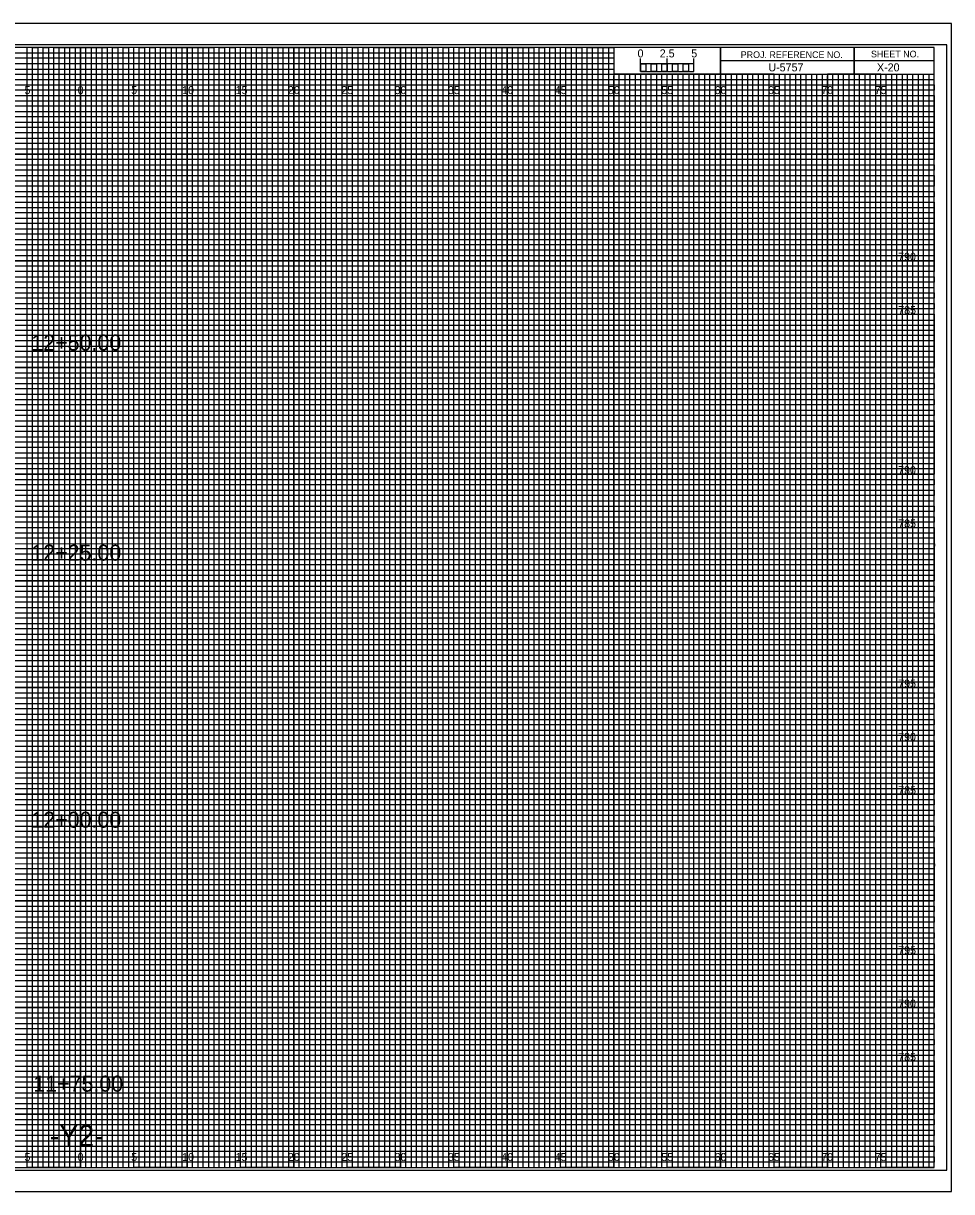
# Model space of a CAD drawing. Extents: x -7 to 162, y 108 to 217.
# Drawn here: x 74.6 to 161.7, y 107.7 to 217.2 of the extents above; entities that cross this region are included whole.
import ezdxf

# ---------------------------------------------------------------- set-up
doc = ezdxf.new("R2010")
doc.units = 0
for name, color, linetype in [('Exist Cross Section Cell', 7, 'Continuous'), ('Exist XS Center Line Elevation Label', 7, 'Continuous'), ('Prop CMT Pvmt Course 2 Wedge', 7, 'Continuous'), ('Prop XS Alignment Label', 7, 'Continuous'), ('Prop XS Bar Scale Labels', 7, 'Continuous'), ('Prop XS Hydro Elevations', 7, 'Continuous'), ('Prop XS Project Number', 7, 'Continuous'), ('Prop XS Retaining Wall', 7, 'Continuous'), ('Prop XS SE Text', 7, 'Continuous'), ('Prop XS Sheet Number', 7, 'Continuous'), ('Prop XS Side Slope Text', 7, 'Continuous'), ('Sheet Cross Section Scale CELL', 7, 'Continuous'), ('Sheet Cutting Line CELL', 7, 'Continuous'), ('Sheet DOT Grid CELL', 7, 'Continuous'), ('Sheet Plot Border Inside CELL', 7, 'Continuous'), ('Sheet Plot Border Outside CELL', 7, 'Continuous')]:
    doc.layers.add(name, color=color, linetype=linetype)

msp = doc.modelspace()

# ---------------------------------------------------------------- linework, layer by layer
at = {"layer": 'Exist Cross Section Cell'}
for p, q in [((75, 215), (70, 215)), ((75, 110), (75, 215)), ((85, 215), (80, 215)), ((80, 215), (80, 110)), ((85, 110), (85, 215)), ((95, 215), (90, 215)), ((90, 215), (90, 110)), ((95, 110), (95, 215)), ((105, 215), (100, 215)), ((100, 215), (100, 110)), ((105, 110), (105, 215)), ((115, 215), (110, 215)), ((110, 215), (110, 110)), ((115, 110), (115, 215)), ((125, 215), (120, 215)), ((120, 215), (120, 110)), ((125, 110), (125, 215)), ((130, 215), (130, 110)), ((135, 110), (135, 212.5)), ((145, 212.5), (140, 212.5)), ((140, 212.5), (140, 110)), ((145, 110), (145, 212.5)), ((155, 212.5), (150, 212.5)), ((150, 212.5), (150, 110)), ((155, 110), (155, 212.5)), ((80, 110), (75, 110)), ((90, 110), (85, 110)), ((100, 110), (95, 110)), ((110, 110), (105, 110)), ((120, 110), (115, 110)), ((130, 110), (125, 110)), ((140, 110), (135, 110)), ((150, 110), (145, 110)), ((160, 110), (155, 110)), ((160, 110), (160, 110))]:
    msp.add_line(p, q, dxfattribs=at)
for points in [[(0, 210), (160, 210), (160, 205), (0, 205)], [(0, 200), (160, 200), (160, 195), (0, 195)], [(0, 190), (160, 190), (160, 185), (0, 185)], [(0, 180), (160, 180), (160, 175), (0, 175)], [(0, 170), (160, 170), (160, 165), (0, 165)], [(0, 160), (160, 160), (160, 155), (0, 155)], [(0, 150), (160, 150), (160, 145), (0, 145)], [(0, 140), (160, 140), (160, 135), (0, 135)], [(0, 130), (160, 130), (160, 125), (0, 125)], [(0, 120), (160, 120), (160, 115), (0, 115)]]:
    msp.add_lwpolyline(points, dxfattribs=at)
at = {"layer": 'Exist XS Center Line Elevation Label'}
for points in [[(72.5, 110), (77.5, 110), (77.5, 215), (82.5, 215), (82.5, 110), (87.5, 110), (87.5, 215), (92.5, 215), (92.5, 110), (97.5, 110), (97.5, 215), (102.5, 215), (102.5, 110), (107.5, 110), (107.5, 215), (112.5, 215), (112.5, 110), (117.5, 110), (117.5, 215), (122.5, 215), (122.5, 110), (127.5, 110), (127.5, 215), (129.97, 215), (130, 215), (130, 212.5), (132.5, 212.5), (132.5, 110), (137.5, 110), (137.5, 212.5), (142.5, 212.5), (142.5, 110), (147.5, 110), (147.5, 212.5), (152.5, 212.5), (152.5, 110), (157.5, 110), (157.5, 212.5)], [(0, 212.5), (137.5, 212.5)], [(0, 202.5), (160, 202.5), (160, 207.5), (0, 207.5)], [(0, 192.5), (160, 192.5), (160, 197.5), (0, 197.5)], [(0, 182.5), (160, 182.5), (160, 187.5), (0, 187.5)], [(0, 172.5), (160, 172.5), (160, 177.5), (0, 177.5)], [(0, 162.5), (160, 162.5), (160, 167.5), (0, 167.5)], [(0, 152.5), (160, 152.5), (160, 157.5), (0, 157.5)], [(0, 142.5), (160, 142.5), (160, 147.5), (0, 147.5)], [(0, 132.5), (160, 132.5), (160, 137.5), (0, 137.5)], [(0, 122.5), (160, 122.5), (160, 127.5), (0, 127.5)], [(0, 112.5), (160, 112.5), (160, 117.5), (0, 117.5)]]:
    msp.add_lwpolyline(points, dxfattribs=at)
at = {"layer": 'Prop XS Hydro Elevations'}
for p, q in [((152.5, 215), (152.5, 212.5)), ((152.5, 212.5), (152.5, 215)), ((160, 213.75), (140, 213.75)), ((140, 213.75), (140, 212.5)), ((140, 212.5), (160, 212.5))]:
    msp.add_line(p, q, dxfattribs=at)
for points in [[(160, 215), (0, 215), (0, 110), (160, 110)], [(140, 215), (130, 215), (130, 212.52), (140, 212.52)], [(160, 215), (140, 215), (140, 212.5), (160, 212.5)]]:
    msp.add_lwpolyline(points, close=True, dxfattribs=at)
at = {"layer": 'Prop XS Retaining Wall'}
for p, q in [((133.5, 212.5), (133, 212.5)), ((133, 212.5), (133, 110)), ((133.5, 110), (133.5, 212.5)), ((134.5, 212.5), (134, 212.5)), ((134, 212.5), (134, 110)), ((134.5, 110), (134.5, 212.5)), ((133, 110), (132.5, 110)), ((134, 110), (133.5, 110))]:
    msp.add_line(p, q, dxfattribs=at)
for points in [[(75, 110), (75.5, 110), (75.5, 215), (76, 215), (76, 110)], [(76, 110), (76.5, 110), (76.5, 215), (77, 215), (77, 110)], [(77.5, 110), (78, 110), (78, 215), (78.5, 215), (78.5, 110)], [(78.5, 110), (79, 110), (79, 215), (79.5, 215), (79.5, 110)], [(80, 110), (80.5, 110), (80.5, 215), (81, 215), (81, 110)], [(81, 110), (81.5, 110), (81.5, 215), (82, 215), (82, 110)], [(82.5, 110), (83, 110), (83, 215), (83.5, 215), (83.5, 110)], [(83.5, 110), (84, 110), (84, 215), (84.5, 215), (84.5, 110)], [(85, 110), (85.5, 110), (85.5, 215), (86, 215), (86, 110)], [(86, 110), (86.5, 110), (86.5, 215), (87, 215), (87, 110)], [(87.5, 110), (88, 110), (88, 215), (88.5, 215), (88.5, 110)], [(88.5, 110), (89, 110), (89, 215), (89.5, 215), (89.5, 110)], [(90, 110), (90.5, 110), (90.5, 215), (91, 215), (91, 110)], [(91, 110), (91.5, 110), (91.5, 215), (92, 215), (92, 110)], [(92.5, 110), (93, 110), (93, 215), (93.5, 215), (93.5, 110)], [(93.5, 110), (94, 110), (94, 215), (94.5, 215), (94.5, 110)], [(95, 110), (95.5, 110), (95.5, 215), (96, 215), (96, 110)], [(96, 110), (96.5, 110), (96.5, 215), (97, 215), (97, 110)], [(97.5, 110), (98, 110), (98, 215), (98.5, 215), (98.5, 110)], [(98.5, 110), (99, 110), (99, 215), (99.5, 215), (99.5, 110)], [(100, 110), (100.5, 110), (100.5, 215), (101, 215), (101, 110)], [(101, 110), (101.5, 110), (101.5, 215), (102, 215), (102, 110)], [(102.5, 110), (103, 110), (103, 215), (103.5, 215), (103.5, 110)], [(103.5, 110), (104, 110), (104, 215), (104.5, 215), (104.5, 110)], [(105, 110), (105.5, 110), (105.5, 215), (106, 215), (106, 110)], [(106, 110), (106.5, 110), (106.5, 215), (107, 215), (107, 110)], [(107.5, 110), (108, 110), (108, 215), (108.5, 215), (108.5, 110)], [(108.5, 110), (109, 110), (109, 215), (109.5, 215), (109.5, 110)], [(110, 110), (110.5, 110), (110.5, 215), (111, 215), (111, 110)], [(111, 110), (111.5, 110), (111.5, 215), (112, 215), (112, 110)], [(112.5, 110), (113, 110), (113, 215), (113.5, 215), (113.5, 110)], [(113.5, 110), (114, 110), (114, 215), (114.5, 215), (114.5, 110)], [(115, 110), (115.5, 110), (115.5, 215), (116, 215), (116, 110)], [(116, 110), (116.5, 110), (116.5, 215), (117, 215), (117, 110)], [(117.5, 110), (118, 110), (118, 215), (118.5, 215), (118.5, 110)], [(118.5, 110), (119, 110), (119, 215), (119.5, 215), (119.5, 110)], [(120, 110), (120.5, 110), (120.5, 215), (121, 215), (121, 110)], [(121, 110), (121.5, 110), (121.5, 215), (122, 215), (122, 110)], [(122.5, 110), (123, 110), (123, 215), (123.5, 215), (123.5, 110)], [(123.5, 110), (124, 110), (124, 215), (124.5, 215), (124.5, 110)], [(125, 110), (125.5, 110), (125.5, 215), (126, 215), (126, 110)], [(126, 110), (126.5, 110), (126.5, 215), (127, 215), (127, 110)], [(127.5, 110), (128, 110), (128, 215), (128.5, 215), (128.5, 110)], [(128.5, 110), (129, 110), (129, 215), (129.5, 215), (129.5, 110)], [(130, 110), (130.5, 110), (130.5, 212.5), (131.01, 212.5), (131.01, 110)], [(131, 110), (131.5, 110), (131.5, 212.5), (132, 212.5), (132, 110)], [(135, 110), (135.49, 110), (135.49, 212.5), (136, 212.5), (136, 110)], [(136, 110), (136.5, 110), (136.5, 212.5), (137.03, 212.5), (137.03, 110)], [(137.5, 110), (138, 110), (138, 212.5), (138.5, 212.5), (138.5, 110)], [(138.5, 110), (139, 110), (139, 212.5), (139.5, 212.5), (139.5, 110)], [(140, 110), (140.5, 110), (140.5, 212.5), (141, 212.5), (141, 110)], [(141, 110), (141.5, 110), (141.5, 212.5), (142, 212.5), (142, 110)], [(142.5, 110), (143, 110), (143, 212.5), (143.5, 212.5), (143.5, 110)], [(143.5, 110), (144, 110), (144, 212.5), (144.5, 212.5), (144.5, 110)], [(145, 110), (145.5, 110), (145.5, 212.5), (146, 212.5), (146, 110)], [(146, 110), (146.5, 110), (146.5, 212.5), (147, 212.5), (147, 110)], [(147.5, 110), (148, 110), (148, 212.5), (148.5, 212.5), (148.5, 110)], [(148.5, 110), (149, 110), (149, 212.5), (149.5, 212.5), (149.5, 110)], [(150, 110), (150.5, 110), (150.5, 212.5), (151, 212.5), (151, 110)], [(151, 110), (151.5, 110), (151.5, 212.5), (152, 212.5), (152, 110)], [(152.5, 110), (153, 110), (153, 212.5), (153.5, 212.5), (153.5, 110)], [(153.5, 110), (154, 110), (154, 212.5), (154.5, 212.5), (154.5, 110)], [(155, 110), (155.5, 110), (155.5, 212.5), (156, 212.5), (156, 110)], [(156, 110), (156.5, 110), (156.5, 212.5), (157, 212.5), (157, 110)], [(157.5, 110), (158, 110), (158, 212.5), (158.5, 212.5), (158.5, 110)], [(158.5, 110), (159, 110), (159, 212.5), (159.5, 212.5), (159.5, 110)]]:
    msp.add_lwpolyline(points, dxfattribs=at)
at = {"layer": 'Prop XS Side Slope Text'}
for p, q in [((0, 214.5), (130, 214.5)), ((130, 213.99), (0, 213.99)), ((130, 214.5), (130, 213.99)), ((0, 213.5), (130, 213.5)), ((130, 212.94), (0, 212.94)), ((130, 213.5), (130, 212.94)), ((0, 212), (160, 212))]:
    msp.add_line(p, q, dxfattribs=at)
for points in [[(0, 211.5), (135, 211.5), (160, 211.5), (160, 211), (0, 211)], [(0, 210.5), (160, 210.5), (160, 209.5), (0, 209.5)], [(0, 209), (160, 209), (160, 208.5), (0, 208.49)], [(0, 208), (160, 208), (160, 207), (0, 207)], [(0, 206.5), (160, 206.5), (160, 206), (0, 206)], [(0, 205.5), (160, 205.5), (160, 204.5), (0, 204.5)], [(0, 204), (160, 204), (160, 203.5), (0, 203.5)], [(0, 203), (160, 203), (160, 202), (0, 202)], [(0, 201.5), (160, 201.5), (160, 201), (0, 201)], [(0, 200.5), (160, 200.5), (160, 199.5), (0, 199.5)], [(0, 199), (160, 199), (160, 198.5), (0, 198.5)], [(0, 198), (160, 198), (160, 196.97), (160, 196.5), (160, 196), (0, 196)], [(0, 197), (160, 197), (160, 196.5), (0, 196.5)], [(0, 195.5), (160, 195.5), (160, 194.5), (0, 194.52)], [(0, 194.52), (160, 194.5), (160, 194), (0, 194)], [(0, 193.5), (160, 193.5), (160, 193), (0, 193)], [(0, 192), (160, 192), (160, 191.5), (0, 191.5)], [(0, 191), (160, 191), (160, 190.5), (0, 190.5)], [(-0.04, 189.44), (160, 189.44), (160, 188.94), (-0.04, 188.94)], [(0, 188.5), (160, 188.5), (160, 188), (0, 188)], [(0, 187), (160, 187), (160, 186.5), (0, 186.5)], [(0, 186), (160, 186), (160, 185.5), (0, 185.5)], [(0, 184.5), (160, 184.5), (160, 184), (0, 184)], [(0, 183.5), (160, 183.5), (160, 183), (0, 183)], [(0, 182), (160, 182), (160, 181.5), (0, 181.5)], [(0, 181), (160, 181), (160, 180.5), (0, 180.5)], [(0, 179.5), (160, 179.5), (160, 178.99), (0, 179)], [(0, 178.5), (160, 178.5), (160, 178), (0, 178)], [(0, 177), (160, 177), (160, 176.5), (0, 176.5)], [(0, 176), (160, 176), (160, 175.5), (0, 175.5)], [(0, 174.5), (160, 174.5), (160, 174), (0, 174)], [(0, 173.5), (160, 173.5), (160, 173), (0, 173)], [(0, 172), (160, 172), (160, 171.5), (0, 171.5)], [(0, 171), (160, 171), (160, 170.5), (0, 170.5)], [(0, 169.5), (160, 169.5), (160, 169), (0, 169)], [(0, 168.5), (160.03, 168.46), (160, 168), (0, 168)], [(0, 167), (160, 167), (160, 166.5), (0, 166.5)], [(0, 166), (160, 166), (160, 165.5), (0, 165.5)], [(0, 164.5), (160, 164.5), (160, 164), (0, 164)], [(0, 163.5), (160, 163.5), (160, 163), (0, 163)], [(0, 162), (160, 162), (160, 161.5), (0, 161.5)], [(0, 161), (160, 161), (160, 160.5), (0, 160.5)], [(0, 159.5), (160, 159.5), (160, 159), (0, 159)], [(0, 158.5), (160, 158.5), (160, 158), (0, 158)], [(0, 157), (160, 157), (160, 156.5), (0, 156.5)], [(0, 156), (160, 156), (160, 155.5), (0, 155.5)], [(0, 154.5), (160, 154.5), (160, 154), (0, 154)], [(0, 153.5), (160, 153.5), (160, 153), (0, 153)], [(0, 152), (160, 152), (160, 151.5), (0, 151.5)], [(0, 151), (160, 151), (160, 150.5), (0, 150.5)], [(0, 149.5), (160, 149.5), (160, 148.99), (0, 149)], [(0, 148.5), (160, 148.5), (160, 148), (0, 148)], [(0, 147), (160, 147), (160, 146.5), (0, 146.5)], [(0, 146), (160, 146), (160, 145.5), (0, 145.5)], [(0, 144.5), (160, 144.5), (160, 144), (0, 144)], [(0, 143.5), (160, 143.5), (160, 143), (0, 143)], [(0, 142), (160, 142), (160, 141.5), (0, 141.5)], [(0, 141), (160, 141), (160, 140.5), (0, 140.5)], [(0, 139.5), (160, 139.5), (160, 139), (0, 139)], [(0, 138.5), (160.03, 138.46), (160, 138), (0, 138)], [(0, 137), (160, 137), (160, 136.5), (0, 136.5)], [(0, 136), (160, 136), (160, 135.5), (0, 135.5)], [(0, 134.5), (160, 134.5), (160, 134), (0, 134)], [(0, 133.5), (160, 133.5), (160, 133), (0, 133)], [(0, 132), (160, 132), (160, 131.5), (0, 131.5)], [(0, 131), (160, 131), (160, 130.5), (0, 130.5)], [(0, 129.5), (160, 129.5), (160, 129), (0, 129)], [(0, 128.5), (160, 128.5), (160, 128), (0, 128)], [(0, 127), (160, 127), (160, 126.5), (0, 126.5)], [(0, 126), (160, 126), (160, 125.5), (0, 125.5)], [(0, 124.5), (160, 124.5), (160, 124), (0, 124)], [(0, 123.5), (160, 123.5), (160, 123), (0, 123)], [(0, 122), (160, 122), (160, 121.5), (0, 121.5)], [(0, 121), (160, 121), (160, 120.5), (0, 120.5)], [(0, 119.5), (160, 119.5), (160, 119), (0, 119)], [(0, 118.5), (160, 118.5), (160, 118), (0, 118)], [(0, 117), (160, 117), (160, 116.5), (0, 116.5)], [(0, 116), (160, 116), (160, 115.5), (0, 115.5)], [(0, 114.5), (160, 114.5), (160, 114), (0, 114)], [(0, 113.5), (160, 113.5), (160, 113), (0, 113)], [(0, 112), (160, 112), (160, 111.5), (0, 111.5)], [(0, 111), (160, 111), (160, 110.5), (0, 110.5)]]:
    msp.add_lwpolyline(points, dxfattribs=at)
at = {"layer": 'Sheet Cross Section Scale CELL'}
for p, q in [((132.5, 212.75), (132.5, 213.95)), ((132.5, 213.45), (132.5, 213.95)), ((135, 212.75), (135, 213.95)), ((137.5, 212.75), (137.5, 213.95)), ((137.5, 213.45), (137.5, 213.95))]:
    msp.add_line(p, q, dxfattribs=at)
for points in [[(137.5, 213.45), (132.5, 213.45), (132.5, 212.75), (137.5, 212.75)], [(132.5, 213.45), (133, 213.45), (133, 212.75), (132.5, 212.75)], [(133.5, 213.45), (134, 213.45), (134, 212.75), (133.5, 212.75)], [(134.5, 213.45), (135, 213.45), (135, 212.75), (134.5, 212.75)], [(135.5, 213.45), (136, 213.45), (136, 212.75), (135.5, 212.75)], [(136.5, 213.45), (137, 213.45), (137, 212.75), (136.5, 212.75)]]:
    msp.add_lwpolyline(points, close=True, dxfattribs=at)
at = {"layer": 'Sheet Cutting Line CELL'}
for p, q in [((161.65, 217.25), (-6.7, 217.25)), ((-6.7, 107.75), (161.65, 107.75))]:
    msp.add_line(p, q, dxfattribs=at)
at = {"layer": 'Sheet DOT Grid CELL'}
for p, q in [((75, 110), (75, 215)), ((80, 110), (80, 215)), ((85, 110), (85, 215)), ((90, 110), (90, 215)), ((95, 110), (95, 215)), ((100, 110), (100, 215)), ((105, 110), (105, 215)), ((110, 110), (110, 215)), ((115, 110), (115, 215)), ((120, 110), (120, 215)), ((125, 110), (125, 215)), ((130, 110), (130, 212.34)), ((135, 110), (135, 212.34)), ((140, 110), (140, 212.34)), ((145, 110), (145, 212.34)), ((150, 110), (150, 212.34)), ((155, 110), (155, 212.34)), ((0, 210), (160, 210)), ((0, 205), (160, 205)), ((0, 200), (160, 200)), ((0, 195), (160, 195)), ((0, 190), (160, 190)), ((0, 185), (160, 185)), ((0, 180), (160, 180)), ((0, 175), (160, 175)), ((0, 170), (160, 170)), ((0, 165), (160, 165)), ((0, 160), (160, 160)), ((0, 155), (160, 155)), ((0, 150), (160, 150)), ((0, 145), (160, 145)), ((0, 140), (160, 140)), ((0, 135), (160, 135)), ((0, 130), (160, 130)), ((0, 125), (160, 125)), ((0, 120), (160, 120)), ((0, 115), (160, 115))]:
    msp.add_line(p, q, dxfattribs=at)
at = {"layer": 'Sheet Plot Border Inside CELL'}
msp.add_lwpolyline([(-5.4, 109.75), (161.2, 109.75), (161.2, 215.25), (-5.4, 215.25)], close=True, dxfattribs=at)
at = {"layer": 'Sheet Plot Border Outside CELL'}
msp.add_lwpolyline([(-6.7, 107.75), (161.65, 107.75), (161.65, 217.25), (-6.7, 217.25)], close=True, dxfattribs=at)

# ---------------------------------------------------------------- texts
at = {"layer": 'Prop CMT Pvmt Course 2 Wedge'}
for s, p in [('790', (156.63, 195)), ('785', (156.64, 190)), ('790', (156.63, 175)), ('785', (156.64, 170)), ('795', (156.64, 155)), ('790', (156.63, 150)), ('785', (156.64, 145)), ('795', (156.64, 130)), ('790', (156.63, 125)), ('785', (156.64, 120))]:
    msp.add_text(s, height=0.75, dxfattribs=at).set_placement(p)
at = {"layer": 'Prop XS Alignment Label'}
msp.add_text('-Y2-', height=2, dxfattribs=at).set_placement((77.12, 112))
at = {"layer": 'Prop XS Bar Scale Labels'}
for s, p in [('2.5', (134.29, 214.06)), ('5', (137.24, 214.06))]:
    msp.add_text(s, height=0.75, dxfattribs=at).set_placement(p)
at = {"layer": 'Prop XS Hydro Elevations'}
for s, p in [('PROJ. REFERENCE NO.', (141.88, 214)), ('SHEET NO.', (154.09, 214.06))]:
    msp.add_text(s, height=0.625, dxfattribs=at).set_placement(p)
at = {"layer": 'Prop XS Project Number'}
msp.add_text('U-5757', height=0.75, dxfattribs=at).set_placement((144.47, 212.75))
at = {"layer": 'Prop XS SE Text'}
for s, height, p in [('5', 0.75, (74.74, 210.62)), ('0', 0.75, (79.73, 210.62)), ('0', 0.75, (79.73, 210.62)), ('5', 0.75, (84.74, 210.62)), ('10', 0.75, (89.52, 210.62)), ('15', 0.75, (94.53, 210.62)), ('20', 0.75, (99.43, 210.62)), ('25', 0.75, (104.44, 210.62)), ('30', 0.75, (109.43, 210.62)), ('35', 0.75, (114.44, 210.62)), ('40', 0.75, (119.43, 210.62)), ('45', 0.75, (124.44, 210.62)), ('50', 0.75, (129.43, 210.62)), ('55', 0.75, (134.44, 210.62)), ('60', 0.75, (139.43, 210.62)), ('65', 0.75, (144.44, 210.62)), ('70', 0.75, (149.43, 210.62)), ('75', 0.75, (154.44, 210.62)), ('12+50.00', 1.5, (75.39, 186.58)), ('12+25.00', 1.5, (75.39, 166.89)), ('12+00.00', 1.5, (75.39, 141.86)), ('11+75.00', 1.5, (75.57, 117.12)), ('5', 0.75, (74.74, 110.62)), ('0', 0.75, (79.73, 110.62)), ('0', 0.75, (79.73, 110.62)), ('5', 0.75, (84.74, 110.62)), ('10', 0.75, (89.52, 110.62)), ('15', 0.75, (94.53, 110.62)), ('20', 0.75, (99.43, 110.62)), ('25', 0.75, (104.44, 110.62)), ('30', 0.75, (109.43, 110.62)), ('35', 0.75, (114.44, 110.62)), ('40', 0.75, (119.43, 110.62)), ('45', 0.75, (124.44, 110.62)), ('50', 0.75, (129.43, 110.62)), ('55', 0.75, (134.44, 110.62)), ('60', 0.75, (139.43, 110.62)), ('65', 0.75, (144.44, 110.62)), ('70', 0.75, (149.43, 110.62)), ('75', 0.75, (154.44, 110.62))]:
    msp.add_text(s, height=height, dxfattribs=at).set_placement(p)
at = {"layer": 'Prop XS Sheet Number'}
msp.add_text('X-20', height=0.75, dxfattribs=at).set_placement((154.65, 212.75))
at = {"layer": 'Sheet Cross Section Scale CELL'}
msp.add_text('0', height=0.75, dxfattribs=at).set_placement((132.21, 214.06))

doc.saveas('drawing.dxf')
